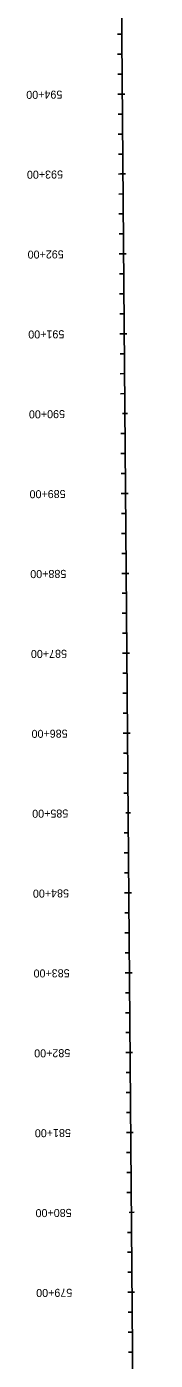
# Model space of a CAD drawing. Extents: x 23417911 to 23421158, y 6737892 to 6791804.
# Drawn here: x 23420728 to 23420889, y 6783385 to 6785055 of the extents above; entities that cross this region are included whole.
import ezdxf

# ---------------------------------------------------------------- set-up
doc = ezdxf.new("R2010")
doc.units = 0
for name, color, linetype in [('Alignment', 7, 'Continuous'), ('TextAlignmentLrg', 7, 'Continuous'), ('TextAlignmentSml', 7, 'Continuous')]:
    doc.layers.add(name, color=color, linetype=linetype)

msp = doc.modelspace()

# ---------------------------------------------------------------- linework, layer by layer
at = {"layer": 'Alignment'}
msp.add_line((23420888.7, 6779969.4), (23420840.8, 6785772.8), dxfattribs=at)
msp.add_line((23420888.7, 6779969.4), (23420840.8, 6785772.8), dxfattribs=at)
at = {"layer": 'TextAlignmentLrg'}
for p, q in [((23420847.5, 6784970.1), (23420842, 6784970)), ((23420848.3, 6784870.1), (23420842.8, 6784870)), ((23420849.1, 6784770.1), (23420843.7, 6784770)), ((23420849.9, 6784670.1), (23420844.5, 6784670)), ((23420847.7, 6784570.1), (23420853.8, 6784570.1)), ((23420851.6, 6784470.1), (23420846.1, 6784470.1)), ((23420852.4, 6784370.1), (23420847, 6784370.1)), ((23420853.2, 6784270.1), (23420847.8, 6784270.1)), ((23420854.1, 6784170.1), (23420848.6, 6784170.1)), ((23420851.8, 6784070.1), (23420857.9, 6784070.1)), ((23420855.7, 6783970.1), (23420850.3, 6783970.1)), ((23420856.5, 6783870.1), (23420851.1, 6783870.1)), ((23420857.4, 6783770.1), (23420851.9, 6783770.1)), ((23420858.2, 6783670.1), (23420852.7, 6783670.1)), ((23420856, 6783570.1), (23420862.1, 6783570.2)), ((23420859.8, 6783470.1), (23420854.4, 6783470.1))]:
    msp.add_line(p, q, dxfattribs=at)
at = {"layer": 'TextAlignmentSml'}
for p, q in [((23420846.8, 6785045.1), (23420841.4, 6785045)), ((23420847.1, 6785020.1), (23420841.6, 6785020)), ((23420847.3, 6784995.1), (23420841.8, 6784995)), ((23420844.4, 6784970.1), (23420850.5, 6784970.1)), ((23420847.7, 6784945.1), (23420842.2, 6784945)), ((23420847.9, 6784920.1), (23420842.4, 6784920)), ((23420848.1, 6784895.1), (23420842.6, 6784895)), ((23420845.2, 6784870.1), (23420851.3, 6784870.1)), ((23420848.5, 6784845.1), (23420843, 6784845)), ((23420848.7, 6784820.1), (23420843.2, 6784820)), ((23420848.9, 6784795.1), (23420843.4, 6784795)), ((23420846.1, 6784770.1), (23420852.2, 6784770.1)), ((23420849.3, 6784745.1), (23420843.9, 6784745)), ((23420849.5, 6784720.1), (23420844.1, 6784720)), ((23420849.7, 6784695.1), (23420844.3, 6784695)), ((23420846.9, 6784670.1), (23420853, 6784670.1)), ((23420850.1, 6784645.1), (23420844.7, 6784645)), ((23420850.4, 6784620.1), (23420844.9, 6784620)), ((23420850.6, 6784595.1), (23420845.1, 6784595)), ((23420847.7, 6784570.1), (23420853.8, 6784570.1)), ((23420851, 6784545.1), (23420845.5, 6784545)), ((23420851.2, 6784520.1), (23420845.7, 6784520)), ((23420851.4, 6784495.1), (23420845.9, 6784495.1)), ((23420848.5, 6784470.1), (23420854.6, 6784470.1)), ((23420851.8, 6784445.1), (23420846.3, 6784445.1)), ((23420852, 6784420.1), (23420846.5, 6784420.1)), ((23420852.2, 6784395.1), (23420846.7, 6784395.1)), ((23420849.4, 6784370.1), (23420855.5, 6784370.1)), ((23420852.6, 6784345.1), (23420847.2, 6784345.1)), ((23420852.8, 6784320.1), (23420847.4, 6784320.1)), ((23420853, 6784295.1), (23420847.6, 6784295.1)), ((23420850.2, 6784270.1), (23420856.3, 6784270.1)), ((23420853.4, 6784245.1), (23420848, 6784245.1)), ((23420853.6, 6784220.1), (23420848.2, 6784220.1)), ((23420853.9, 6784195.1), (23420848.4, 6784195.1)), ((23420851, 6784170.1), (23420857.1, 6784170.1)), ((23420854.3, 6784145.1), (23420848.8, 6784145.1)), ((23420854.5, 6784120.1), (23420849, 6784120.1)), ((23420854.7, 6784095.1), (23420849.2, 6784095.1)), ((23420851.8, 6784070.1), (23420857.9, 6784070.1)), ((23420855.1, 6784045.1), (23420849.6, 6784045.1)), ((23420855.3, 6784020.1), (23420849.8, 6784020.1)), ((23420855.5, 6783995.1), (23420850, 6783995.1)), ((23420852.7, 6783970.1), (23420858.8, 6783970.1)), ((23420855.9, 6783945.1), (23420850.5, 6783945.1)), ((23420856.1, 6783920.1), (23420850.7, 6783920.1)), ((23420856.3, 6783895.1), (23420850.9, 6783895.1)), ((23420853.5, 6783870.1), (23420859.6, 6783870.1)), ((23420856.7, 6783845.1), (23420851.3, 6783845.1)), ((23420856.9, 6783820.1), (23420851.5, 6783820.1)), ((23420857.2, 6783795.1), (23420851.7, 6783795.1)), ((23420854.3, 6783770.1), (23420860.4, 6783770.1)), ((23420857.6, 6783745.1), (23420852.1, 6783745.1)), ((23420857.8, 6783720.1), (23420852.3, 6783720.1)), ((23420858, 6783695.1), (23420852.5, 6783695.1)), ((23420855.1, 6783670.1), (23420861.2, 6783670.1)), ((23420858.4, 6783645.1), (23420852.9, 6783645.1)), ((23420858.6, 6783620.1), (23420853.1, 6783620.1)), ((23420858.8, 6783595.1), (23420853.3, 6783595.1)), ((23420856, 6783570.1), (23420862.1, 6783570.2)), ((23420859.2, 6783545.1), (23420853.8, 6783545.1)), ((23420859.4, 6783520.1), (23420854, 6783520.1)), ((23420859.6, 6783495.1), (23420854.2, 6783495.1)), ((23420856.8, 6783470.1), (23420862.9, 6783470.2)), ((23420860, 6783445.1), (23420854.6, 6783445.1)), ((23420860.2, 6783420.1), (23420854.8, 6783420.1)), ((23420860.5, 6783395.1), (23420855, 6783395.1))]:
    msp.add_line(p, q, dxfattribs=at)

# ---------------------------------------------------------------- texts
at = {"layer": 'TextAlignmentLrg'}
for s, p in [('590+00', (23420775.7, 6784574.5)), ('585+00', (23420779.8, 6784074.5)), ('580+00', (23420784, 6783574.5))]:
    msp.add_text(s, height=10.02, rotation=180.4726, dxfattribs=at).set_placement(p)
at = {"layer": 'TextAlignmentSml'}
for s, p in [('594+00', (23420772.4, 6784974.5)), ('593+00', (23420773.2, 6784874.5)), ('592+00', (23420774.1, 6784774.5)), ('591+00', (23420774.9, 6784674.5)), ('590+00', (23420775.7, 6784574.5)), ('589+00', (23420776.5, 6784474.5)), ('588+00', (23420777.4, 6784374.5)), ('587+00', (23420778.2, 6784274.5)), ('586+00', (23420779, 6784174.5)), ('585+00', (23420779.8, 6784074.5)), ('584+00', (23420780.7, 6783974.5)), ('583+00', (23420781.5, 6783874.5)), ('582+00', (23420782.3, 6783774.5)), ('581+00', (23420783.1, 6783674.5)), ('580+00', (23420784, 6783574.5)), ('579+00', (23420784.8, 6783474.5))]:
    msp.add_text(s, height=10.02, rotation=180.4726, dxfattribs=at).set_placement(p)

doc.saveas('drawing.dxf')
